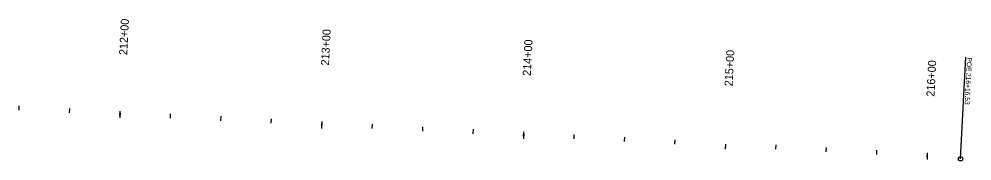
# Model space of a CAD drawing. Extents: x 20499876 to 20505320, y 7953544 to 7954108.
# Drawn here: x 20504848.1 to 20505319.7, y 7953617.9 to 7953688.2 of the extents above; entities that cross this region are included whole.
import ezdxf

# ---------------------------------------------------------------- set-up
doc = ezdxf.new("R2010")
doc.units = 0
for name, color, linetype in [('Curb', 7, 'Continuous'), ('Draft_7', 7, 'Continuous'), ('Text', 7, 'Continuous')]:
    doc.layers.add(name, color=color, linetype=linetype)

msp = doc.modelspace()

# ---------------------------------------------------------------- linework, layer by layer
at = {"layer": 'Curb'}
for p, q in [((20504898.08, 7953640.38), (20504898.19, 7953642.57)), ((20504997.95, 7953635.24), (20504998.06, 7953637.42)), ((20505097.82, 7953630.09), (20505097.93, 7953632.27)), ((20505197.75, 7953626.16), (20505197.62, 7953623.72)), ((20505297.55, 7953619.79), (20505297.66, 7953621.97))]:
    msp.add_line(p, q, dxfattribs=at)
at = {"layer": 'Draft_7'}
for p, q in [((20504848.15, 7953642.96), (20504848.26, 7953645.14)), ((20504873.11, 7953641.67), (20504873.23, 7953643.85)), ((20504898.14, 7953641.61), (20504898.02, 7953639.16)), ((20504923.05, 7953639.1), (20504923.16, 7953641.28)), ((20504948.01, 7953637.81), (20504948.13, 7953639.99)), ((20504972.98, 7953636.52), (20504973.09, 7953638.7)), ((20504998.01, 7953636.46), (20504997.89, 7953634.01)), ((20505022.91, 7953633.95), (20505023.03, 7953636.13)), ((20505047.88, 7953632.66), (20505047.99, 7953634.84)), ((20505072.85, 7953631.37), (20505072.96, 7953633.55)), ((20505097.88, 7953631.31), (20505097.75, 7953628.86)), ((20505122.78, 7953628.8), (20505122.89, 7953630.98)), ((20505147.75, 7953627.51), (20505147.86, 7953629.69)), ((20505172.72, 7953626.23), (20505172.83, 7953628.41)), ((20505197.75, 7953626.16), (20505197.62, 7953623.72)), ((20505222.65, 7953623.65), (20505222.76, 7953625.83)), ((20505247.62, 7953622.36), (20505247.73, 7953624.54)), ((20505272.58, 7953621.08), (20505272.7, 7953623.26)), ((20505297.61, 7953621.01), (20505297.49, 7953618.57))]:
    msp.add_line(p, q, dxfattribs=at)
at = {"layer": 'Text'}
for p in [(20505314.06, 7953618.94), (20505316.66, 7953669.27)]:
    msp.add_line(p, (20505316.66, 7953669.27), dxfattribs=at)
msp.add_circle((20505314.06, 7953618.94), 1.07, dxfattribs=at)

# ---------------------------------------------------------------- texts
at = {"layer": 'Curb'}
msp.add_text('215+00', height=4.008, rotation=87.0487, dxfattribs=at).set_placement((20505201.23, 7953654.79))
at = {"layer": 'Draft_7'}
for s, p in [('212+00', (20504901.63, 7953670.24)), ('213+00', (20505001.49, 7953665.09)), ('214+00', (20505101.36, 7953659.94)), ('215+00', (20505201.23, 7953654.79)), ('216+00', (20505301.1, 7953649.65))]:
    msp.add_text(s, height=4.008, rotation=87.0487, dxfattribs=at).set_placement(p)
at = {"layer": 'Text'}
for s, p in [('POE ', (20505317.3, 7953669.24)), ('216+16.53', (20505316.91, 7953661.54))]:
    msp.add_text(s, height=2.4, rotation=267.0487, dxfattribs=at).set_placement(p)

doc.saveas('drawing.dxf')
